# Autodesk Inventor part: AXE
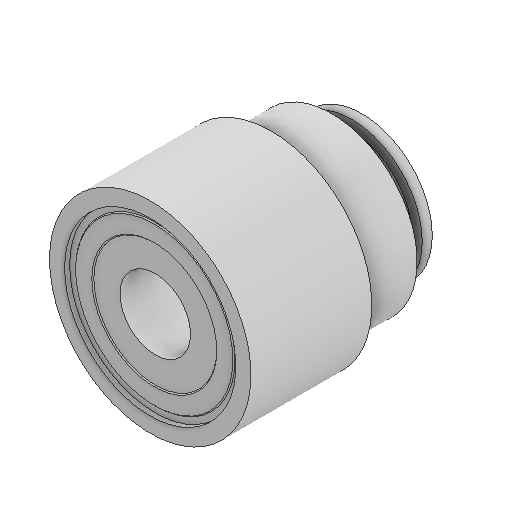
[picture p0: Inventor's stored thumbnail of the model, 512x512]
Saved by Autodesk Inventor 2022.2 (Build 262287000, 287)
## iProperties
Created: 2025-01
Part Number: AXE
Material: Generico
Document SubType Name: Modeling
Designer: 18907419
Density: 1 g/cm^3
Appearance: Default
Author: 18907419
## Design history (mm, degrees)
feature "AXE"
node "Solido1"
